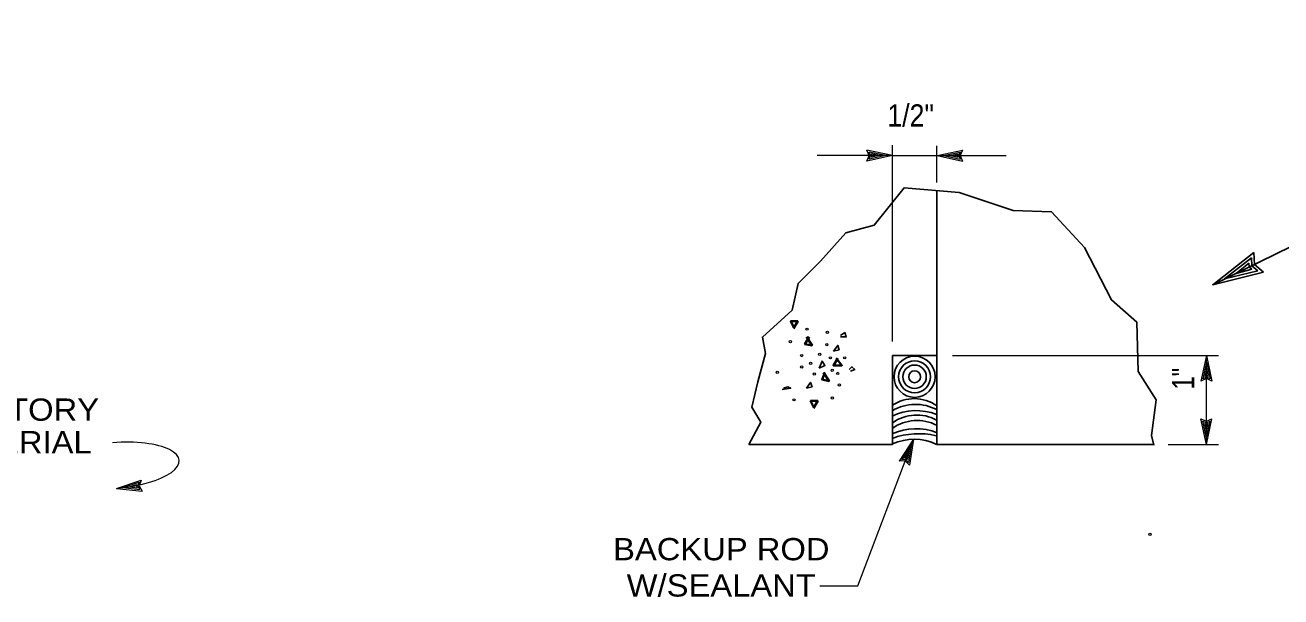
# Model space of a CAD drawing. Extents: x -22.3 to 19.7, y -11.8 to 18.2.
# Drawn here: x 5.45 to 12.51, y -3.03 to 0.18 of the extents above; entities that cross this region are included whole.
import ezdxf
from ezdxf.enums import TextEntityAlignment as Align

# ---------------------------------------------------------------- set-up
doc = ezdxf.new("R2010")
doc.units = 0
doc.header["$LTSCALE"] = 0.05
doc.layers.add('1', color=7, linetype='Continuous', lineweight=13)
doc.layers.add('2', color=7, linetype='Continuous', lineweight=13)

msp = doc.modelspace()

# ---------------------------------------------------------------- linework, layer by layer
at = {"layer": '1'}
for p, q in [((10.32358, -0.55469), (9.90158, -0.55469)), ((10.32358, -0.55469), (10.17958, -0.52369)), ((10.32358, -0.55469), (10.17958, -0.58569)), ((10.28658, -0.55469), (10.19258, -0.53469)), ((10.20158, -0.55469), (10.19258, -0.53469)), ((10.28658, -0.55469), (10.19258, -0.57469)), ((10.19258, -0.57469), (10.20158, -0.55469)), ((10.25058, -0.55469), (10.20558, -0.54569)), ((10.21058, -0.55469), (10.20558, -0.54569)), ((10.25058, -0.55469), (10.20558, -0.56369)), ((10.20558, -0.56369), (10.21058, -0.55469)), ((10.32358, -1.59969), (10.32358, -0.49669)), ((10.32358, -0.55469), (10.57458, -0.55469)), ((10.57358, -0.70669), (10.57358, -0.49969)), ((10.57458, -0.55469), (10.71858, -0.52369)), ((10.57458, -0.55469), (10.96358, -0.55469)), ((10.57458, -0.55469), (10.71858, -0.58569)), ((10.61158, -0.55469), (10.70558, -0.53469)), ((10.61158, -0.55469), (10.70558, -0.57469)), ((10.64758, -0.55469), (10.69258, -0.54569)), ((10.64758, -0.55469), (10.69258, -0.56369)), ((10.69258, -0.54569), (10.68758, -0.55469)), ((10.68758, -0.55469), (10.69258, -0.56369)), ((10.70558, -0.53469), (10.69658, -0.55469)), ((10.69658, -0.55469), (10.70558, -0.57469)), ((10.66158, -1.67769), (12.15558, -1.67769)), ((12.08858, -1.67769), (12.05758, -1.82169)), ((12.08858, -2.17769), (12.08858, -1.67769)), ((12.08858, -1.67769), (12.11958, -1.82169)), ((12.08858, -1.71469), (12.06858, -1.80869)), ((12.08858, -1.75069), (12.07958, -1.79569)), ((12.08858, -1.71469), (12.10858, -1.80869)), ((12.08858, -1.75069), (12.09758, -1.79569)), ((12.08858, -1.79969), (12.06858, -1.80869)), ((12.08858, -1.79069), (12.07958, -1.79569)), ((12.09758, -1.79569), (12.08858, -1.79069)), ((12.10858, -1.80869), (12.08858, -1.79969)), ((12.08858, -2.17769), (12.05758, -2.03369)), ((12.08858, -2.17769), (12.11958, -2.03369)), ((12.08858, -2.14069), (12.06858, -2.04669)), ((12.06858, -2.04669), (12.08858, -2.05569)), ((12.08858, -2.10469), (12.07958, -2.05969)), ((12.07958, -2.05969), (12.08858, -2.06469)), ((12.08858, -2.14069), (12.10858, -2.04669)), ((12.08858, -2.05569), (12.10858, -2.04669)), ((12.08858, -2.10469), (12.09758, -2.05969)), ((12.08858, -2.06469), (12.09758, -2.05969)), ((10.44258, -2.14869), (10.36258, -2.27269)), ((10.42958, -2.18269), (10.37758, -2.26369)), ((10.42958, -2.18269), (10.41458, -2.27869)), ((11.87358, -2.17769), (12.15558, -2.17769)), ((10.41658, -2.21769), (10.39158, -2.25569)), ((10.40258, -2.25469), (10.39158, -2.25569)), ((10.40958, -2.26269), (10.40258, -2.25469)), ((10.41658, -2.21769), (10.40958, -2.26269)), ((10.39958, -2.26269), (10.37758, -2.26369)), ((10.41458, -2.27869), (10.39958, -2.26269)), ((5.96358, -2.42469), (6.10358, -2.37869)), ((6.00058, -2.42069), (6.09158, -2.39069)), ((6.09158, -2.39069), (6.08458, -2.41169)), ((5.96358, -2.42469), (6.10958, -2.44069)), ((6.00058, -2.42069), (6.09558, -2.43069)), ((6.03658, -2.41669), (6.07958, -2.40269)), ((6.03658, -2.41669), (6.08158, -2.42169)), ((6.07958, -2.40269), (6.07658, -2.41269)), ((6.07658, -2.41269), (6.08158, -2.42169)), ((6.08458, -2.41169), (6.09558, -2.43069)), ((9.91658, -2.97269), (10.12958, -2.97269))]:
    msp.add_line(p, q, dxfattribs=at)
at = {"layer": '1', "lineweight": 25}
for p, q in [((10.57358, -2.17769), (10.57358, -0.75169)), ((12.18958, -1.24769), (12.34158, -1.12969)), ((12.25458, -1.21669), (12.32658, -1.15869)), ((12.25458, -1.21669), (12.34358, -1.19269)), ((12.32658, -1.15869), (12.32858, -1.18069)), ((12.32858, -1.18069), (12.34358, -1.19269)), ((12.34158, -1.12969), (12.34258, -1.17369)), ((12.34258, -1.17369), (12.37658, -1.20169)), ((12.12358, -1.28069), (12.40958, -1.20969)), ((12.18958, -1.24769), (12.37658, -1.20169)), ((10.57358, -1.67769), (10.32358, -1.67769)), ((10.32358, -2.17769), (10.32358, -1.67769)), ((10.32458, -2.17769), (9.51758, -2.17769)), ((11.79158, -2.17769), (10.57358, -2.17769))]:
    msp.add_line(p, q, dxfattribs=at)
for points in [[(15.10558, 0.17831), (12.12358, -1.28069), (12.35458, -1.09869)], [(9.51758, -2.17769), (9.58558, -2.05269), (9.53458, -1.96869), (9.56858, -1.82569), (9.61058, -1.66669), (9.59358, -1.57469), (9.76058, -1.42369), (9.79458, -1.27269), (9.92058, -1.14769), (10.06258, -0.98869), (10.22158, -0.94669), (10.38958, -0.73669), (10.69958, -0.76169), (11.00158, -0.86269), (11.21858, -0.87069), (11.40358, -1.07169), (11.55458, -1.36569), (11.69658, -1.49069), (11.70558, -1.76769), (11.80558, -1.92669), (11.78058, -2.12769), (11.79258, -2.18269)], [(12.35458, -1.09869), (12.35758, -1.16669), (12.40958, -1.20969)]]:
    msp.add_lwpolyline(points, dxfattribs=at)
at = {"layer": '1'}
for points in [[(10.17958, -0.58569), (10.19358, -0.55469), (10.17958, -0.52369)], [(10.71858, -0.52369), (10.70458, -0.55469), (10.71858, -0.58569)], [(12.11958, -1.82169), (12.08858, -1.80769), (12.05758, -1.82169)], [(12.05758, -2.03369), (12.08858, -2.04769), (12.11958, -2.03369)], [(10.12958, -2.97269), (10.44258, -2.14869), (10.42058, -2.29469)], [(10.42058, -2.29469), (10.39658, -2.26969), (10.36258, -2.27269)], [(6.10358, -2.37869), (6.09258, -2.41069), (6.10958, -2.44069)]]:
    msp.add_lwpolyline(points, dxfattribs=at)
at = {"layer": '1', "lineweight": 25}
for radius in [0.11562, 0.08966, 0.06574, 0.03322]:
    msp.add_circle((10.44858, -1.79769), radius, dxfattribs=at)
for centre, radius, start, end in [((10.4466, -2.14347), 0.22282, 55.56929, 123.51031), ((10.45344, -2.20477), 0.2521, 61.2788, 121.0036), ((10.45817, -2.29085), 0.30317, 68.03259, 116.56701), ((10.46269, -2.28834), 0.24473, 62.79314, 124.92555), ((10.46074, -2.24915), 0.23657, 61.78579, 125.13672), ((10.45605, -2.40942), 0.31991, 68.05894, 114.65814), ((10.47165, -2.54736), 0.42997, 76.83496, 110.14369), ((10.44537, -2.4422), 0.29352, 64.31494, 114.29894)]:
    msp.add_arc(centre, radius, start, end, dxfattribs=at)
at = {"layer": '1'}
msp.add_ellipse((5.95308, -2.29669), major_axis=(-0.36324, -0.0298), ratio=0.352382, start_param=1.5707963, end_param=4.712389, dxfattribs=at)
at = {"layer": '2', "lineweight": 25}
msp.add_line((10.03258, -1.56569), (10.05658, -1.54969), dxfattribs=at)
at = {"layer": '2', "lineweight": 35}
for points in [[(9.76858, -1.51769), (9.75258, -1.48569), (9.79258, -1.48569), (9.76858, -1.52569)], [(9.85658, -1.57369), (9.83258, -1.61369), (9.87258, -1.62169), (9.84058, -1.57369)], [(10.01658, -1.69369), (9.99258, -1.73369), (10.04058, -1.73369), (10.00858, -1.69369)], [(9.94458, -1.77369), (9.92858, -1.81369), (9.96858, -1.82169), (9.93658, -1.77369)], [(9.88058, -1.96569), (9.86458, -1.93369), (9.90458, -1.93369), (9.88058, -1.97369)]]:
    msp.add_lwpolyline(points, dxfattribs=at)
at = {"layer": '2', "lineweight": 25}
for points in [[(10.05658, -1.54969), (10.06458, -1.57369), (10.03258, -1.57369)], [(10.08058, -1.75769), (10.09658, -1.74169), (10.11258, -1.75769), (10.08858, -1.76569)], [(9.71258, -1.86169), (9.73658, -1.85369), (9.75258, -1.86169), (9.70458, -1.86969)]]:
    msp.add_lwpolyline(points, dxfattribs=at)
for points in [[(9.99258, -1.65369), (10.01658, -1.62169), (10.02458, -1.64569)], [(9.91258, -1.74969), (9.92858, -1.70969), (9.94458, -1.73369)], [(9.84058, -1.86169), (9.86458, -1.82969), (9.87258, -1.85369)]]:
    msp.add_lwpolyline(points, close=True, dxfattribs=at)
at = {"layer": '2'}
for centre in [(9.84458, -1.53019), (9.95858, -1.54719), (9.75058, -1.60019), (9.95558, -1.61719), (9.81458, -1.67819), (9.91558, -1.67119), (9.97558, -1.69119), (10.05658, -1.69119), (9.81458, -1.74219), (9.86458, -1.72219), (9.98558, -1.76219), (9.67658, -1.77219), (9.88458, -1.78219), (10.01658, -1.77919), (10.02658, -1.84319), (9.77058, -1.92719), (9.98658, -1.91719), (11.77058, -2.68219)]:
    msp.add_circle(centre, 0.0065, dxfattribs=at)

# ---------------------------------------------------------------- texts
at = {"layer": '1'}
for s, width, p in [('1/2"', 0.9, (10.55758, -0.39169)), ('BACKUP ROD', 1.1, (9.97058, -2.82869)), ('W/SEALANT', 1.1, (9.89358, -3.03269))]:
    msp.add_text(s, height=0.125, dxfattribs=dict(at, width=width)).set_placement(p, align=Align.RIGHT)
at = {"layer": '1', "width": 0.8}
msp.add_text('1"', height=0.125, rotation=90, dxfattribs=at).set_placement((12.01958, -1.74769), align=Align.RIGHT)
at = {"layer": '1', "width": 1.1}
for s, p in [('SATISFACTORY', (5.16158, -2.04469)), ('FILL MATERIAL', (5.15558, -2.22769))]:
    msp.add_text(s, height=0.125, dxfattribs=at).set_placement(p, align=Align.CENTER)

doc.saveas('drawing.dxf')
